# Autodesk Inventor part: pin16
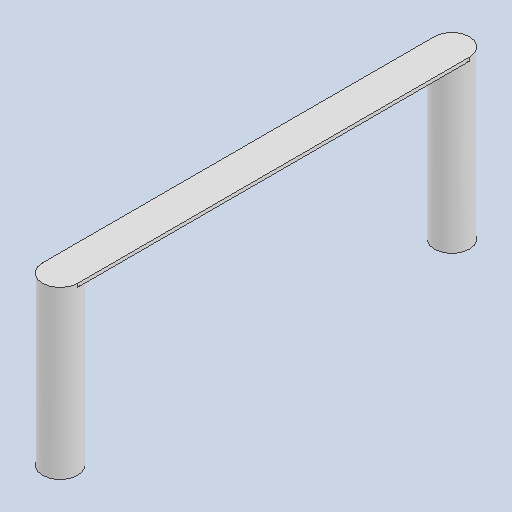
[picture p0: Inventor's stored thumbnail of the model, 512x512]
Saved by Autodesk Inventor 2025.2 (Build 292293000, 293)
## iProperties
Created: 2025-04
Part Number: pin16
Material: Generic
Description: PART--DESC
Document SubType Name: Modeling
Designer: BennF
Density: 1 g/cm^3
Appearance: Default
Author: BennF
Revision Number: NONE
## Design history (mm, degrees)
feature "Solid"
body "Solid1"
